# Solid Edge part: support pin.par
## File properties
Author: Sarvanan
Template: sync ansi part.par
Last saved by: Cadcim
Revision: 3
Application: Solid Edge
Accuracy: 0.990
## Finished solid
Body 1: solid body, 8 faces, 7 edges, 0 vertices.
  Faces by surface: plane 4, cylinder 3, cone 1
  Edges by curve: circle 7
Bounding box of the edges (mm): 6.350 x 6.350 x 66.675, from (12.0753, 27.1097, -66.675) to (18.4253, 33.4597, 0).
Cylindrical faces by radius (mm): R2.413 x2, R3.175 x1
Conical faces (half-angle, radius in mm at the cone's reference point): 44.9733 deg R1.6517 x1
Planar faces by outward normal: +z 2, -z 2
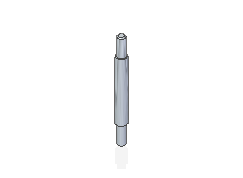
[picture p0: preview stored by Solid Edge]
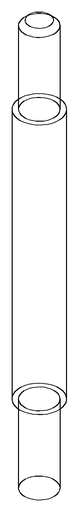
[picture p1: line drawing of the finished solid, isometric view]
